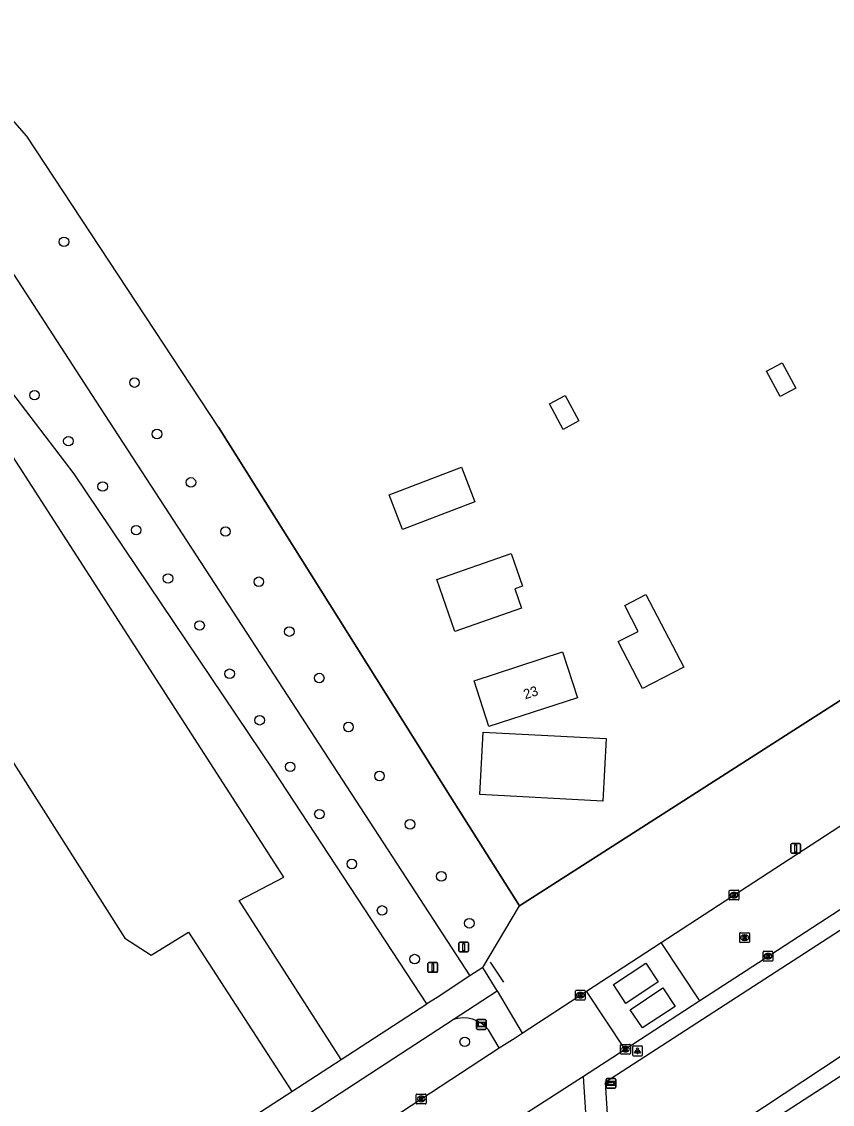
# Model space of a CAD drawing. Extents: x 159451 to 160663, y 388402 to 389723.
# Drawn here: x 159830.6 to 159913.3, y 389268.1 to 389378.7 of the extents above; entities that cross this region are included whole.
import ezdxf

# ---------------------------------------------------------------- set-up
doc = ezdxf.new("R2010")
doc.units = 0
for name, color, linetype in [('IMGEO_Afsluitpaal', 7, 'Continuous'), ('IMGEO_Berm_groen', 7, 'Continuous'), ('IMGEO_Berm_open', 7, 'Continuous'), ('IMGEO_Boom', 7, 'Continuous'), ('IMGEO_Fietspad_gesloten', 7, 'Continuous'), ('IMGEO_Fietspad_open', 7, 'Continuous'), ('IMGEO_Hek', 7, 'Continuous'), ('IMGEO_Kolk', 7, 'Continuous'), ('IMGEO_Lichtpunt', 7, 'Continuous'), ('IMGEO_Loofbos', 7, 'Continuous'), ('IMGEO_Meer_plas_ven_vijver', 7, 'Continuous'), ('IMGEO_Muur', 7, 'Continuous'), ('IMGEO_Pand', 7, 'Continuous'), ('IMGEO_Pand_nummerreeks', 7, 'Continuous'), ('IMGEO_Pand_vergunning_verleend', 7, 'Continuous'), ('IMGEO_Parkeervlak_halfverhard', 7, 'Continuous'), ('IMGEO_Rijbaan_lokaal_gesloten', 7, 'Continuous'), ('IMGEO_Rijbaan_lokaal_open', 7, 'Continuous'), ('IMGEO_Rioolput', 7, 'Continuous'), ('IMGEO_Straatnaambord', 7, 'Continuous'), ('IMGEO_Verkeersbordpaal', 7, 'Continuous'), ('IMGEO_Wegwijzer', 7, 'Continuous')]:
    doc.layers.add(name, color=color, linetype=linetype)

msp = doc.modelspace()

# ---------------------------------------------------------------- linework, layer by layer
at = {"layer": 'IMGEO_Afsluitpaal'}
for p, q in [((159875.21, 389283.72), (159875.21, 389284.52)), ((159875.21, 389284.52), (159875.21, 389283.72)), ((159875.31, 389284.62), (159876.1, 389284.62)), ((159876.1, 389284.62), (159875.31, 389284.62)), ((159876.2, 389284.52), (159876.2, 389283.72)), ((159876.2, 389283.72), (159876.2, 389284.52)), ((159876.1, 389283.62), (159875.31, 389283.62)), ((159875.31, 389283.62), (159876.1, 389283.62)), ((159872.06, 389281.64), (159872.06, 389282.44)), ((159872.06, 389282.44), (159872.06, 389281.64)), ((159872.16, 389282.54), (159872.95, 389282.54)), ((159872.95, 389282.54), (159872.16, 389282.54)), ((159872.95, 389281.54), (159872.16, 389281.54)), ((159872.16, 389281.54), (159872.95, 389281.54)), ((159873.05, 389282.44), (159873.05, 389281.64)), ((159873.05, 389281.64), (159873.05, 389282.44))]:
    msp.add_line(p, q, dxfattribs=at)
for points in [[(159875.63, 389284.49), (159875.78, 389284.49), (159875.78, 389283.74), (159875.63, 389283.74), (159875.63, 389284.49)], [(159872.48, 389282.41), (159872.63, 389282.41), (159872.63, 389281.66), (159872.48, 389281.66), (159872.48, 389282.41)]]:
    msp.add_lwpolyline(points, dxfattribs=at)
for centre, start, end in [((159875.31, 389284.52), 90, 180), ((159875.31, 389284.52), 90, 180), ((159875.31, 389283.72), 180, 270), ((159875.31, 389283.72), 180, 270), ((159876.1, 389284.52), 0, 90), ((159876.1, 389284.52), 360, 90), ((159876.1, 389283.72), 270, 0), ((159876.1, 389283.72), 270, 0), ((159872.16, 389282.44), 90, 180), ((159872.16, 389282.44), 90, 180), ((159872.16, 389281.64), 180, 270), ((159872.16, 389281.64), 180, 270), ((159872.95, 389282.44), 0, 90), ((159872.95, 389282.44), 360, 90), ((159872.95, 389281.64), 270, 0), ((159872.95, 389281.64), 270, 0)]:
    msp.add_arc(centre, 0.1, start, end, dxfattribs=at)
at = {"layer": 'IMGEO_Berm_groen'}
for points in [[(160039.49, 389376.11), (160004.13, 389366.97), (159881.39, 389288.32)], [(159900.41, 389263.84), (159994.26, 389325.91), (160002.52, 389330.32)], [(159877.68, 389282.04), (159881.39, 389288.32)]]:
    msp.add_lwpolyline(points, dxfattribs=at)
at = {"layer": 'IMGEO_Berm_open'}
msp.add_lwpolyline([(160002.81, 389340.25), (160000.75, 389338.88), (159999.17, 389341.19), (159962.36, 389317.3), (159918.72, 389288.76), (159890.17, 389270.29), (159890.42, 389265.99), (159893.33, 389261.45), (159891.48, 389260.21)], dxfattribs=at)
at = {"layer": 'IMGEO_Boom'}
for centre in [(159834.9, 389356.17), (159842.1, 389341.79), (159831.89, 389340.5), (159844.4, 389336.53), (159835.35, 389335.8), (159838.85, 389331.17), (159847.86, 389331.59), (159842.27, 389326.71), (159851.39, 389326.57), (159845.52, 389321.77), (159854.79, 389321.44), (159848.74, 389316.97), (159857.91, 389316.35), (159851.81, 389312.04), (159860.96, 389311.6), (159854.88, 389307.29), (159863.95, 389306.6), (159857.99, 389302.53), (159867.11, 389301.6), (159860.98, 389297.7), (159870.23, 389296.66), (159864.29, 389292.61), (159873.43, 389291.34), (159867.38, 389287.86), (159876.29, 389286.55), (159870.7, 389282.89), (159875.82, 389274.44)]:
    msp.add_circle(centre, 0.489, dxfattribs=at)
at = {"layer": 'IMGEO_Fietspad_gesloten'}
for points in [[(159877.68, 389282.04), (159876.34, 389281.17)], [(159879.11, 389279.64), (159877.68, 389282.04)], [(159876.34, 389281.17), (159872.99, 389278.98), (159871.96, 389278.31)], [(159874.62, 389276.71), (159879.11, 389279.64)], [(159863.19, 389272.62), (159871.96, 389278.31)], [(159832.31, 389249.12), (159833.66, 389250), (159874.62, 389276.71)], [(159858.15, 389269.35), (159863.19, 389272.62)], [(159787.28, 389223.36), (159792.67, 389226.89), (159858.15, 389269.35)]]:
    msp.add_lwpolyline(points, dxfattribs=at)
at = {"layer": 'IMGEO_Fietspad_open'}
for points in [[(159879.11, 389279.64), (159881.68, 389275.33)], [(159879.33, 389273.81), (159878.24, 389275.65)]]:
    msp.add_lwpolyline(points, dxfattribs=at)
msp.add_arc((159875.68, 389273.6), 3.28, 38.73, 108.7521, dxfattribs=at)
at = {"layer": 'IMGEO_Hek'}
msp.add_lwpolyline([(159878.4, 389282.57), (159879.76, 389280.52)], dxfattribs=at)
at = {"layer": 'IMGEO_Kolk'}
for p, q in [((159902.81, 389289.01), (159902.81, 389289.86)), ((159902.88, 389289.93), (159903.74, 389289.93)), ((159903.3, 389289.71), (159903.32, 389289.71)), ((159903.81, 389289.86), (159903.81, 389289.01)), ((159903.74, 389288.93), (159902.88, 389288.93)), ((159903.32, 389289.15), (159903.29, 389289.15)), ((159906.27, 389282.76), (159906.27, 389283.61)), ((159906.35, 389283.69), (159907.2, 389283.69)), ((159907.2, 389282.68), (159906.35, 389282.68)), ((159906.76, 389283.46), (159906.79, 389283.46)), ((159906.78, 389282.91), (159906.76, 389282.91)), ((159907.28, 389283.61), (159907.28, 389282.76)), ((159887.12, 389278.78), (159887.12, 389279.63)), ((159887.19, 389279.7), (159888.05, 389279.7)), ((159887.61, 389279.48), (159887.63, 389279.48)), ((159888.12, 389279.63), (159888.12, 389278.78)), ((159888.05, 389278.7), (159887.19, 389278.7)), ((159887.63, 389278.92), (159887.6, 389278.92)), ((159891.73, 389273.25), (159891.73, 389274.1)), ((159891.8, 389274.18), (159892.66, 389274.18)), ((159892.22, 389273.96), (159892.24, 389273.96)), ((159892.73, 389274.1), (159892.73, 389273.25)), ((159892.66, 389273.18), (159891.8, 389273.18)), ((159892.24, 389273.4), (159892.21, 389273.4)), ((159870.87, 389268.17), (159870.87, 389269.03)), ((159870.94, 389269.1), (159871.79, 389269.1)), ((159871.38, 389268.32), (159871.35, 389268.32)), ((159871.36, 389268.88), (159871.38, 389268.88)), ((159871.87, 389269.03), (159871.87, 389268.17)), ((159871.79, 389268.1), (159870.94, 389268.1))]:
    msp.add_line(p, q, dxfattribs=at)
for points in [[(159902.81, 389289.01), (159902.81, 389289.86)], [(159902.88, 389289.93), (159903.74, 389289.93)], [(159903.13, 389289.63), (159903.25, 389289.63), (159903.25, 389289.48), (159903.38, 389289.63), (159903.55, 389289.63), (159903.4, 389289.48), (159903.55, 389289.23), (159903.4, 389289.23), (159903.32, 389289.4), (159903.25, 389289.33), (159903.25, 389289.23), (159903.13, 389289.23), (159903.13, 389289.63)], [(159903.81, 389289.86), (159903.81, 389289.01)], [(159903.74, 389288.93), (159902.88, 389288.93)], [(159906.27, 389282.76), (159906.27, 389283.61)], [(159906.35, 389283.69), (159907.2, 389283.69)], [(159907.2, 389282.68), (159906.35, 389282.68)], [(159906.59, 389283.38), (159906.72, 389283.38), (159906.72, 389283.23), (159906.85, 389283.38), (159907.01, 389283.38), (159906.87, 389283.23), (159907.02, 389282.98), (159906.87, 389282.98), (159906.78, 389283.15), (159906.72, 389283.08), (159906.72, 389282.98), (159906.59, 389282.98), (159906.59, 389283.38)], [(159907.28, 389283.61), (159907.28, 389282.76)], [(159887.12, 389278.78), (159887.12, 389279.63)], [(159887.19, 389279.7), (159888.05, 389279.7)], [(159887.44, 389279.4), (159887.56, 389279.4), (159887.56, 389279.25), (159887.69, 389279.4), (159887.86, 389279.4), (159887.71, 389279.25), (159887.86, 389279), (159887.71, 389279), (159887.63, 389279.17), (159887.56, 389279.1), (159887.56, 389279), (159887.44, 389279), (159887.44, 389279.4)], [(159888.12, 389279.63), (159888.12, 389278.78)], [(159888.05, 389278.7), (159887.19, 389278.7)], [(159891.73, 389273.25), (159891.73, 389274.1)], [(159891.8, 389274.18), (159892.66, 389274.18)], [(159892.05, 389273.88), (159892.17, 389273.88), (159892.17, 389273.73), (159892.3, 389273.88), (159892.47, 389273.88), (159892.32, 389273.73), (159892.47, 389273.48), (159892.32, 389273.48), (159892.24, 389273.64), (159892.17, 389273.57), (159892.17, 389273.48), (159892.05, 389273.48), (159892.05, 389273.88)], [(159892.73, 389274.1), (159892.73, 389273.25)], [(159892.66, 389273.18), (159891.8, 389273.18)], [(159870.87, 389268.17), (159870.87, 389269.03)], [(159870.94, 389269.1), (159871.79, 389269.1)], [(159871.19, 389268.8), (159871.31, 389268.8), (159871.31, 389268.65), (159871.44, 389268.8), (159871.61, 389268.8), (159871.46, 389268.65), (159871.61, 389268.4), (159871.46, 389268.4), (159871.38, 389268.56), (159871.31, 389268.5), (159871.31, 389268.4), (159871.19, 389268.4), (159871.19, 389268.8)], [(159871.87, 389269.03), (159871.87, 389268.17)], [(159871.79, 389268.1), (159870.94, 389268.1)]]:
    msp.add_lwpolyline(points, dxfattribs=at)
for centre, start, end in [((159902.89, 389289.86), 91.552, 178.448), ((159902.89, 389289.86), 91.552, 178.448), ((159903.73, 389289.86), 1.552, 88.448), ((159903.73, 389289.86), 1.552, 88.448), ((159902.89, 389289.01), 181.552, 268.448), ((159902.89, 389289.01), 181.552, 268.448), ((159903.73, 389289.01), 271.552, 358.448), ((159903.73, 389289.01), 271.552, 358.448), ((159906.35, 389283.61), 91.552, 178.448), ((159906.35, 389283.61), 91.552, 178.448), ((159906.35, 389282.76), 181.552, 268.448), ((159906.35, 389282.76), 181.552, 268.448), ((159907.2, 389283.61), 1.552, 88.448), ((159907.2, 389283.61), 1.552, 88.448), ((159907.2, 389282.76), 271.552, 358.448), ((159907.2, 389282.76), 271.552, 358.448), ((159887.2, 389279.63), 91.552, 178.448), ((159887.2, 389279.63), 91.552, 178.448), ((159888.04, 389279.63), 1.552, 88.448), ((159888.04, 389279.63), 1.552, 88.448), ((159887.2, 389278.78), 181.552, 268.448), ((159887.2, 389278.78), 181.552, 268.448), ((159888.04, 389278.78), 271.552, 358.448), ((159888.04, 389278.78), 271.552, 358.448), ((159891.81, 389274.1), 91.552, 178.448), ((159891.81, 389274.1), 91.552, 178.448), ((159892.65, 389274.1), 1.552, 88.448), ((159892.65, 389274.1), 1.552, 88.448), ((159891.81, 389273.25), 181.552, 268.448), ((159891.81, 389273.25), 181.552, 268.448), ((159892.65, 389273.25), 271.552, 358.448), ((159892.65, 389273.25), 271.552, 358.448), ((159870.94, 389269.02), 91.552, 178.448), ((159870.94, 389269.02), 91.552, 178.448), ((159871.79, 389269.02), 1.552, 88.448), ((159871.79, 389269.02), 1.552, 88.448), ((159870.94, 389268.17), 181.552, 268.448), ((159870.94, 389268.17), 181.552, 268.448), ((159871.79, 389268.17), 271.552, 358.448), ((159871.79, 389268.17), 271.552, 358.448)]:
    msp.add_arc(centre, 0.0765, start, end, dxfattribs=at)
for centre, major_axis, ratio, start_param, end_param in [((159903.3, 389289.43), (-0.387, 0.002), 0.722429, 4.712389, 7.853982), ((159903.32, 389289.43), (-0.39, 0.002), 0.717154, 1.570796, 4.712389), ((159906.76, 389283.18), (-0.387, 0.002), 0.722429, 4.712389, 7.853982), ((159906.79, 389283.18), (-0.39, 0.002), 0.717154, 1.570796, 4.712389), ((159887.61, 389279.2), (-0.387, 0.002), 0.722429, 4.712389, 7.853982), ((159887.63, 389279.2), (-0.39, 0.002), 0.717154, 1.570796, 4.712389), ((159892.22, 389273.68), (-0.387, 0.002), 0.722429, 4.712389, 7.853982), ((159892.24, 389273.68), (-0.39, 0.002), 0.717154, 1.570796, 4.712389), ((159871.35, 389268.6), (-0.387, 0.002), 0.722429, 4.712389, 7.853982), ((159871.38, 389268.6), (-0.39, 0.002), 0.717154, 1.570796, 4.712389)]:
    msp.add_ellipse(centre, major_axis=major_axis, ratio=ratio, start_param=start_param, end_param=end_param, dxfattribs=at)
at = {"layer": 'IMGEO_Lichtpunt'}
for p, q in [((159892.96, 389273.92), (159892.96, 389273.11)), ((159892.96, 389273.92), (159892.96, 389273.11)), ((159893.86, 389274.01), (159893.05, 389274.01)), ((159893.86, 389274.01), (159893.05, 389274.01)), ((159893.96, 389273.11), (159893.96, 389273.92)), ((159893.96, 389273.11), (159893.96, 389273.92)), ((159893.05, 389273.02), (159893.86, 389273.02)), ((159893.05, 389273.02), (159893.86, 389273.02))]:
    msp.add_line(p, q, dxfattribs=at)
for points in [[(159893.33, 389273.58), (159893.37, 389273.55), (159893.18, 389273.29), (159893.15, 389273.32), (159893.33, 389273.58)], [(159893.43, 389273.53), (159893.48, 389273.53), (159893.48, 389273.21), (159893.43, 389273.21), (159893.43, 389273.53)], [(159893.54, 389273.55), (159893.58, 389273.58), (159893.77, 389273.32), (159893.73, 389273.29), (159893.54, 389273.55)]]:
    msp.add_lwpolyline(points, dxfattribs=at)
msp.add_circle((159893.46, 389273.72), 0.0994, dxfattribs=at)
for centre, start, end in [((159893.05, 389273.92), 90, 180), ((159893.05, 389273.92), 90, 180), ((159893.86, 389273.92), 0, 90), ((159893.86, 389273.92), 0, 90), ((159893.05, 389273.11), 180, 270), ((159893.05, 389273.11), 180, 270), ((159893.86, 389273.11), 270, 0), ((159893.86, 389273.11), 270, 360)]:
    msp.add_arc(centre, 0.0946, start, end, dxfattribs=at)
at = {"layer": 'IMGEO_Loofbos'}
for points in [[(159871.96, 389278.31), (159856.3, 389302.19), (159835.93, 389332.46), (159821.1, 389351.87), (159816.71, 389357.62), (159791.04, 389385.41), (159788.61, 389359.57), (159782.92, 389353.41), (159786.17, 389346.9), (159774.32, 389338.96), (159772.15, 389341.51), (159744.65, 389323.51), (159741.65, 389327.63), (159762.21, 389343.03), (159732.27, 389382.65), (159734.43, 389384.27), (159705.43, 389419.91), (159686.88, 389439.01), (159667.95, 389454.31), (159663.03, 389457.69), (159684.18, 389485.7), (159690.1, 389492.47), (159692.72, 389500)], [(159881.39, 389288.32), (159874.34, 389299.54), (159850.68, 389337.23), (159831.1, 389366.95), (159811.91, 389388.9), (159794.48, 389423.34)], [(159782.84, 389411.56), (159827.32, 389356.54), (159838.14, 389339.9), (159876.34, 389281.17)]]:
    msp.add_lwpolyline(points, dxfattribs=at)
at = {"layer": 'IMGEO_Meer_plas_ven_vijver'}
msp.add_lwpolyline([(159900.67, 389263.49), (159902.08, 389263.09), (159920.61, 389275.11), (159928.8, 389280.79), (159947.84, 389293.11), (159962.25, 389302.44), (159981.5, 389314.97), (160001.38, 389326.86), (160001.83, 389327.11), (160002.29, 389327.32), (160002.88, 389327.47), (160003.26, 389327.48), (160003.97, 389327.29), (160004.23, 389327.16), (160004.67, 389326.73), (160004.83, 389326.39), (160004.89, 389325.67), (160004.84, 389325.36), (160004.67, 389324.92), (160004.34, 389324.52), (160003.95, 389324.2), (160000, 389321.66), (159944.67, 389285.75), (159903.35, 389257.91)], dxfattribs=at)
at = {"layer": 'IMGEO_Muur'}
for points in [[(159881.39, 389288.32), (160004.13, 389366.97), (160039.49, 389376.11)], [(159850.68, 389337.23), (159874.34, 389299.54)], [(159874.34, 389299.54), (159881.39, 389288.32)]]:
    msp.add_lwpolyline(points, dxfattribs=at)
at = {"layer": 'IMGEO_Pand'}
msp.add_lwpolyline([(159887.34, 389309.58), (159878.29, 389306.65), (159876.78, 389311.33), (159885.8, 389314.28), (159887.34, 389309.58)], dxfattribs=at)
at = {"layer": 'IMGEO_Pand_vergunning_verleend'}
for points in [[(159906.61, 389342.97), (159908.21, 389343.82), (159909.61, 389341.21), (159908.01, 389340.35), (159906.61, 389342.97)], [(159884.47, 389339.62), (159886.07, 389340.48), (159887.47, 389337.87), (159885.87, 389337.01), (159884.47, 389339.62)], [(159868.11, 389330.31), (159875.47, 389333.15), (159876.84, 389329.61), (159869.47, 389326.77), (159868.11, 389330.31)], [(159872.96, 389321.68), (159880.55, 389324.32), (159881.72, 389320.98), (159880.92, 389320.7), (159881.61, 389318.73), (159874.81, 389316.36), (159872.96, 389321.68)], [(159891.49, 389315.32), (159893.52, 389316.37), (159892.15, 389319.02), (159894.31, 389320.14), (159898.17, 389312.7), (159893.98, 389310.53), (159891.49, 389315.32)], [(159877.37, 389299.69), (159877.7, 389306.08), (159890.24, 389305.44), (159889.91, 389299.04), (159877.37, 389299.69)]]:
    msp.add_lwpolyline(points, dxfattribs=at)
at = {"layer": 'IMGEO_Parkeervlak_halfverhard'}
msp.add_lwpolyline([(159863.19, 389272.62), (159852.77, 389288.88), (159857.34, 389291.26), (159817.62, 389352.91), (159803.63, 389343.97), (159841.12, 389285.04), (159843.81, 389283.3), (159847.62, 389285.65), (159858.15, 389269.35)], dxfattribs=at)
at = {"layer": 'IMGEO_Rijbaan_lokaal_gesloten'}
for points in [[(159895.87, 389284.58), (159930.8, 389307.35), (159986.35, 389343.16), (160000, 389351.61), (160005.85, 389355.23), (160011.54, 389358.23), (160022.23, 389362.94), (160022.75, 389363.16), (160024.31, 389363.83), (160036.11, 389368.42)], [(159998.77, 389342.96), (159973.82, 389326.76), (159947.89, 389309.89), (159906.38, 389282.87), (159899.83, 389278.61)], [(159892.25, 389278.36), (159891, 389280.29), (159894.31, 389282.47), (159895.55, 389280.58), (159892.25, 389278.36)], [(159881.68, 389275.33), (159888.24, 389279.61)], [(159893.95, 389275.88), (159892.71, 389277.72), (159896.05, 389279.94), (159897.29, 389278.06), (159893.95, 389275.88)], [(159879.33, 389273.81), (159880.95, 389274.86), (159881.68, 389275.33)], [(159837.72, 389246.59), (159838.01, 389246.78), (159842.33, 389249.6), (159842.95, 389250), (159855.43, 389258.17), (159879.33, 389273.81)], [(159892.21, 389273.65), (159887.95, 389270.88)], [(159887.95, 389270.88), (159878.69, 389264.93)]]:
    msp.add_lwpolyline(points, dxfattribs=at)
at = {"layer": 'IMGEO_Rijbaan_lokaal_open'}
for points in [[(159888.24, 389279.61), (159895.87, 389284.58)], [(159899.83, 389278.61), (159895.87, 389284.58)], [(159892.21, 389273.65), (159888.24, 389279.61)], [(159899.83, 389278.61), (159892.21, 389273.65)], [(159891.48, 389260.21), (159888.32, 389265.1), (159887.95, 389270.88)]]:
    msp.add_lwpolyline(points, dxfattribs=at)
at = {"layer": 'IMGEO_Rioolput'}
for p, q in [((159903.89, 389284.66), (159903.89, 389285.51)), ((159903.96, 389285.58), (159904.82, 389285.58)), ((159904.38, 389285.36), (159904.4, 389285.36)), ((159904.89, 389285.51), (159904.89, 389284.66)), ((159904.82, 389284.58), (159903.96, 389284.58)), ((159904.4, 389284.8), (159904.37, 389284.8))]:
    msp.add_line(p, q, dxfattribs=at)
for points in [[(159903.89, 389284.66), (159903.89, 389285.51)], [(159903.96, 389285.58), (159904.82, 389285.58)], [(159904.48, 389285.28), (159904.22, 389285.28), (159904.22, 389284.88)], [(159904.22, 389284.88), (159904.35, 389284.88), (159904.35, 389285.05), (159904.36, 389285.05)], [(159904.4, 389285.2), (159904.35, 389285.2), (159904.35, 389285.12)], [(159904.35, 389285.12), (159904.4, 389285.12)], [(159904.41, 389285.02), (159904.48, 389284.88), (159904.62, 389284.88), (159904.55, 389285.01)], [(159904.89, 389285.51), (159904.89, 389284.66)], [(159904.82, 389284.58), (159903.96, 389284.58)]]:
    msp.add_lwpolyline(points, dxfattribs=at)
for centre, radius, start, end in [((159903.96, 389285.51), 0.0765, 91.552, 178.448), ((159903.96, 389285.51), 0.0765, 91.552, 178.448), ((159904.36, 389284.99), 0.0533, 26.0293, 88.6989), ((159904.41, 389285.11), 0.0964, 77.0061, 93.1865), ((159904.39, 389285.31), 0.19, 274.7715, 282.9687), ((159904.42, 389285.16), 0.0378, 276.6634, 79.6772), ((159904.48, 389285.17), 0.109, 350.3612, 89.416), ((159904.47, 389285.17), 0.112, 277.5842, 350.9817), ((159904.46, 389284.96), 0.108, 29.5134, 73.7905), ((159904.81, 389285.51), 0.0765, 1.552, 88.448), ((159904.81, 389285.51), 0.0765, 1.552, 88.448), ((159903.96, 389284.66), 0.0765, 181.552, 268.448), ((159903.96, 389284.66), 0.0765, 181.552, 268.448), ((159904.81, 389284.66), 0.0765, 271.552, 358.448), ((159904.81, 389284.66), 0.0765, 271.552, 358.448)]:
    msp.add_arc(centre, radius, start, end, dxfattribs=at)
for centre, major_axis, ratio, start_param, end_param in [((159904.38, 389285.08), (-0.387, 0.002), 0.722429, 4.712389, 7.853982), ((159904.4, 389285.08), (-0.39, 0.002), 0.717154, 1.570796, 4.712389)]:
    msp.add_ellipse(centre, major_axis=major_axis, ratio=ratio, start_param=start_param, end_param=end_param, dxfattribs=at)
at = {"layer": 'IMGEO_Straatnaambord'}
for p, q in [((159877.01, 389275.81), (159877.01, 389276.61)), ((159877.01, 389276.61), (159877.01, 389275.81)), ((159877.11, 389276.71), (159877.9, 389276.71)), ((159877.9, 389276.71), (159877.11, 389276.71)), ((159878, 389276.61), (159878, 389275.81)), ((159878, 389275.81), (159878, 389276.61)), ((159877.9, 389275.71), (159877.11, 389275.71)), ((159877.11, 389275.71), (159877.9, 389275.71))]:
    msp.add_line(p, q, dxfattribs=at)
for points in [[(159877.12, 389276.45), (159877.9, 389276.45), (159877.9, 389275.98), (159877.12, 389275.98), (159877.12, 389276.45)], [(159877.18, 389276.38), (159877.18, 389276.05), (159877.84, 389276.05), (159877.84, 389276.38), (159877.18, 389276.38)]]:
    msp.add_lwpolyline(points, dxfattribs=at)
for centre, start, end in [((159877.11, 389276.61), 90, 180), ((159877.11, 389276.61), 90, 180), ((159877.9, 389276.61), 0, 90), ((159877.9, 389276.61), 360, 90), ((159877.11, 389275.81), 180, 270), ((159877.11, 389275.81), 180, 270), ((159877.9, 389275.81), 270, 0), ((159877.9, 389275.81), 270, 0)]:
    msp.add_arc(centre, 0.1, start, end, dxfattribs=at)
at = {"layer": 'IMGEO_Verkeersbordpaal'}
for p, q in [((159909.12, 389293.8), (159909.12, 389294.6)), ((159909.12, 389294.6), (159909.12, 389293.8)), ((159909.22, 389294.7), (159910, 389294.7)), ((159910, 389294.7), (159909.22, 389294.7)), ((159910, 389293.7), (159909.22, 389293.7)), ((159909.22, 389293.7), (159910, 389293.7)), ((159910.1, 389294.6), (159910.1, 389293.8)), ((159910.1, 389293.8), (159910.1, 389294.6))]:
    msp.add_line(p, q, dxfattribs=at)
msp.add_lwpolyline([(159909.53, 389294.57), (159909.68, 389294.57), (159909.68, 389293.82), (159909.53, 389293.82), (159909.53, 389294.57)], dxfattribs=at)
for centre, start, end in [((159909.22, 389294.6), 90, 180), ((159909.22, 389294.6), 90, 180), ((159909.22, 389293.8), 180, 270), ((159909.22, 389293.8), 180, 270), ((159910, 389294.6), 0, 90), ((159910, 389294.6), 360, 90), ((159910, 389293.8), 270, 0), ((159910, 389293.8), 270, 0)]:
    msp.add_arc(centre, 0.1, start, end, dxfattribs=at)
at = {"layer": 'IMGEO_Wegwijzer'}
for p, q in [((159890.26, 389269.8), (159890.26, 389270.6)), ((159890.26, 389270.6), (159890.26, 389269.8)), ((159890.36, 389270.7), (159891.15, 389270.7)), ((159891.15, 389270.7), (159890.36, 389270.7)), ((159891.25, 389270.6), (159891.25, 389269.8)), ((159891.25, 389269.8), (159891.25, 389270.6)), ((159891.15, 389269.7), (159890.36, 389269.7)), ((159890.36, 389269.7), (159891.15, 389269.7))]:
    msp.add_line(p, q, dxfattribs=at)
for points in [[(159890.37, 389270.43), (159891.15, 389270.43), (159891.15, 389269.96), (159890.37, 389269.96), (159890.37, 389270.43)], [(159890.43, 389270.28), (159890.43, 389270.2), (159890.43, 389270.11), (159890.84, 389270.11), (159890.84, 389270.03), (159891.09, 389270.2), (159890.84, 389270.36), (159890.84, 389270.28), (159890.43, 389270.28)]]:
    msp.add_lwpolyline(points, dxfattribs=at)
for centre, start, end in [((159890.36, 389270.6), 90, 180), ((159890.36, 389270.6), 90, 180), ((159891.15, 389270.6), 0, 90), ((159891.15, 389270.6), 360, 90), ((159890.36, 389269.8), 180, 270), ((159890.36, 389269.8), 180, 270), ((159891.15, 389269.8), 270, 0), ((159891.15, 389269.8), 270, 0)]:
    msp.add_arc(centre, 0.1, start, end, dxfattribs=at)

# ---------------------------------------------------------------- texts
at = {"layer": 'IMGEO_Pand_nummerreeks'}
msp.add_text('23', height=1, rotation=17.9278, dxfattribs=at).set_placement((159881.99, 389309.42))

doc.saveas('drawing.dxf')
